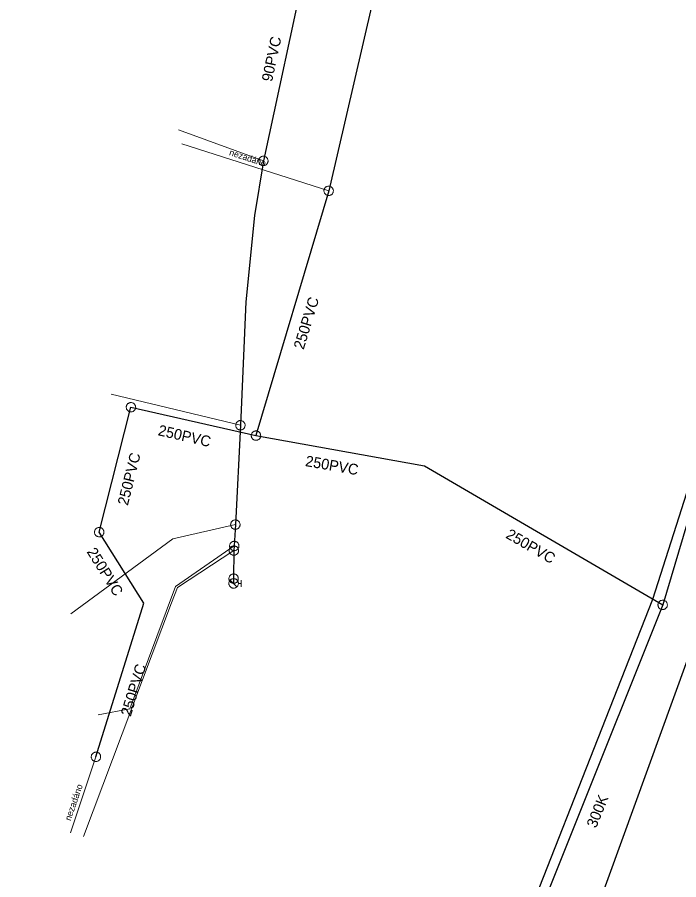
# Model space of a CAD drawing. Extents: x -741806 to -738704, y -1059275 to -1055387.
# Drawn here: x -740595 to -740533.4, y -1057880.2 to -1057799.9 of the extents above; entities that cross this region are included whole.
import ezdxf

# ---------------------------------------------------------------- set-up
doc = ezdxf.new("R2010")
doc.units = 0
doc.header["$LTSCALE"] = 0.4
for name, color, linetype, lineweight in [('2', 7, 'Continuous', 25), ('21', 7, 'Continuous', 13), ('3', 7, 'Continuous', 13), ('50', 7, 'Continuous', 13), ('51', 7, 'Continuous', 13), ('52', 7, 'Continuous', 25), ('56', 7, 'Continuous', 13)]:
    doc.layers.add(name, color=color, linetype=linetype, lineweight=lineweight)
for name, color, linetype in [('5', 7, 'Continuous'), ('53', 7, 'Continuous'), ('55', 7, 'Continuous')]:
    doc.layers.add(name, color=color, linetype=linetype)

msp = doc.modelspace()

# ---------------------------------------------------------------- linework, layer by layer
at = {"layer": '2'}
for p, q in [((-740566.01, -1057816.08), (-740572.78, -1057838.879)), ((-740584.42, -1057836.24), (-740572.78, -1057838.879)), ((-740529.84, -1057837.59), (-740534.91, -1057854.649)), ((-740572.78, -1057838.879), (-740557.1, -1057841.679)), ((-740557.1, -1057841.679), (-740534.91, -1057854.649)), ((-740587.68, -1057868.8), (-740583.21, -1057854.49))]:
    msp.add_line(p, q, dxfattribs=at)
for points in [[(-740609.006, -1057979.487), (-740608.671, -1057978.605), (-740585.671, -1057978.608), (-740567.046, -1057933.639), (-740552.184, -1057895.72), (-740535.835, -1057854.115), (-740530.462, -1057837.318), (-740525.059, -1057820.845), (-740524.232, -1057813.604), (-740512.355, -1057767.872), (-740507.212, -1057752.35), (-740500.784, -1057723.652), (-740491.688, -1057677.854), (-740489.039, -1057665.21)], [(-740555.449, -1057770.34), (-740559.17, -1057786.49), (-740559.609, -1057788.399), (-740566.01, -1057816.08)], [(-740583.21, -1057854.49), (-740587.379, -1057847.87), (-740584.42, -1057836.24)], [(-740534.91, -1057854.649), (-740551.41, -1057895.909), (-740566.21, -1057933.99)]]:
    msp.add_lwpolyline(points, dxfattribs=at)
at = {"layer": '21'}
for p, q in [((-740572.09, -1057813.29), (-740580, -1057810.399)), ((-740574.23, -1057837.919), (-740586.26, -1057835.02))]:
    msp.add_line(p, q, dxfattribs=at)
for points in [[(-740574.699, -1057847.169), (-740580.53, -1057848.49), (-740590.02, -1057855.48)], [(-740574.84, -1057849.59), (-740580.1, -1057853.02), (-740580.66, -1057854.47), (-740588.829, -1057876.21)], [(-740574.8, -1057849.159), (-740580.28, -1057852.919), (-740584.539, -1057864.33), (-740587.46, -1057864.899)]]:
    msp.add_lwpolyline(points, dxfattribs=at)
at = {"layer": '3'}
for points in [[(-740566.109, -1057816.506), (-740566.064, -1057816.513), (-740566.019, -1057816.517), (-740565.972, -1057816.515), (-740565.928, -1057816.509), (-740565.883, -1057816.498), (-740565.839, -1057816.482), (-740565.799, -1057816.462), (-740565.759, -1057816.438), (-740565.724, -1057816.409), (-740565.691, -1057816.378), (-740565.661, -1057816.343), (-740565.635, -1057816.305), (-740565.614, -1057816.264), (-740565.597, -1057816.222), (-740565.584, -1057816.178), (-740565.576, -1057816.133), (-740565.573, -1057816.087), (-740565.574, -1057816.042), (-740565.581, -1057815.996), (-740565.592, -1057815.951), (-740565.608, -1057815.909), (-740565.628, -1057815.868), (-740565.652, -1057815.829), (-740565.68, -1057815.792), (-740565.712, -1057815.759), (-740565.748, -1057815.731), (-740565.785, -1057815.704), (-740565.826, -1057815.683), (-740565.868, -1057815.666), (-740565.913, -1057815.653), (-740565.957, -1057815.645), (-740566.002, -1057815.642), (-740566.049, -1057815.643), (-740566.095, -1057815.65), (-740566.138, -1057815.661), (-740566.182, -1057815.676), (-740566.222, -1057815.697), (-740566.262, -1057815.721), (-740566.297, -1057815.749), (-740566.33, -1057815.781), (-740566.36, -1057815.816), (-740566.386, -1057815.854), (-740566.407, -1057815.894), (-740566.424, -1057815.936), (-740566.437, -1057815.981), (-740566.445, -1057816.026), (-740566.448, -1057816.071), (-740566.447, -1057816.117), (-740566.44, -1057816.163), (-740566.429, -1057816.207), (-740566.413, -1057816.25), (-740566.394, -1057816.291), (-740566.369, -1057816.33), (-740566.341, -1057816.366), (-740566.309, -1057816.399), (-740566.274, -1057816.429), (-740566.236, -1057816.454), (-740566.195, -1057816.476), (-740566.153, -1057816.493), (-740566.11, -1057816.506)], [(-740584.311, -1057835.815), (-740584.355, -1057835.807), (-740584.401, -1057835.803), (-740584.447, -1057835.803), (-740584.492, -1057835.808), (-740584.537, -1057835.819), (-740584.581, -1057835.833), (-740584.622, -1057835.853), (-740584.662, -1057835.876), (-740584.698, -1057835.903), (-740584.731, -1057835.934), (-740584.762, -1057835.969), (-740584.789, -1057836.006), (-740584.81, -1057836.046), (-740584.829, -1057836.088), (-740584.843, -1057836.132), (-740584.852, -1057836.177), (-740584.855, -1057836.222), (-740584.855, -1057836.268), (-740584.85, -1057836.314), (-740584.839, -1057836.359), (-740584.824, -1057836.402), (-740584.806, -1057836.442), (-740584.782, -1057836.483), (-740584.755, -1057836.519), (-740584.724, -1057836.553), (-740584.689, -1057836.583), (-740584.652, -1057836.609), (-740584.612, -1057836.632), (-740584.57, -1057836.65), (-740584.526, -1057836.663), (-740584.482, -1057836.673), (-740584.436, -1057836.677), (-740584.39, -1057836.676), (-740584.344, -1057836.67), (-740584.3, -1057836.661), (-740584.256, -1057836.646), (-740584.215, -1057836.627), (-740584.175, -1057836.603), (-740584.139, -1057836.576), (-740584.106, -1057836.545), (-740584.075, -1057836.511), (-740584.048, -1057836.473), (-740584.026, -1057836.434), (-740584.008, -1057836.392), (-740583.995, -1057836.348), (-740583.985, -1057836.303), (-740583.981, -1057836.257), (-740583.982, -1057836.212), (-740583.987, -1057836.166), (-740583.998, -1057836.121), (-740584.013, -1057836.078), (-740584.031, -1057836.036), (-740584.055, -1057835.997), (-740584.082, -1057835.96), (-740584.113, -1057835.926), (-740584.148, -1057835.896), (-740584.185, -1057835.87), (-740584.225, -1057835.847), (-740584.267, -1057835.829), (-740584.31, -1057835.815)], [(-740572.352, -1057838.976), (-740572.345, -1057838.931), (-740572.342, -1057838.886), (-740572.344, -1057838.839), (-740572.35, -1057838.795), (-740572.362, -1057838.75), (-740572.378, -1057838.707), (-740572.398, -1057838.666), (-740572.422, -1057838.627), (-740572.451, -1057838.592), (-740572.482, -1057838.559), (-740572.518, -1057838.529), (-740572.556, -1057838.503), (-740572.596, -1057838.483), (-740572.639, -1057838.465), (-740572.683, -1057838.453), (-740572.728, -1057838.445), (-740572.774, -1057838.442), (-740572.819, -1057838.443), (-740572.865, -1057838.45), (-740572.91, -1057838.462), (-740572.952, -1057838.478), (-740572.992, -1057838.497), (-740573.032, -1057838.522), (-740573.068, -1057838.55), (-740573.101, -1057838.583), (-740573.13, -1057838.618), (-740573.155, -1057838.655), (-740573.177, -1057838.697), (-740573.194, -1057838.739), (-740573.206, -1057838.783), (-740573.214, -1057838.828), (-740573.217, -1057838.873), (-740573.215, -1057838.92), (-740573.208, -1057838.965), (-740573.198, -1057839.009), (-740573.182, -1057839.052), (-740573.161, -1057839.093), (-740573.136, -1057839.132), (-740573.109, -1057839.167), (-740573.077, -1057839.2), (-740573.042, -1057839.23), (-740573.004, -1057839.256), (-740572.963, -1057839.277), (-740572.921, -1057839.294), (-740572.876, -1057839.306), (-740572.831, -1057839.314), (-740572.786, -1057839.317), (-740572.74, -1057839.316), (-740572.694, -1057839.308), (-740572.65, -1057839.297), (-740572.607, -1057839.281), (-740572.566, -1057839.262), (-740572.527, -1057839.237), (-740572.491, -1057839.209), (-740572.458, -1057839.176), (-740572.429, -1057839.141), (-740572.404, -1057839.104), (-740572.382, -1057839.062), (-740572.366, -1057839.02), (-740572.353, -1057838.977)], [(-740587.612, -1057847.499), (-740587.648, -1057847.525), (-740587.682, -1057847.555), (-740587.714, -1057847.589), (-740587.741, -1057847.625), (-740587.765, -1057847.665), (-740587.784, -1057847.707), (-740587.798, -1057847.75), (-740587.809, -1057847.795), (-740587.814, -1057847.84), (-740587.815, -1057847.885), (-740587.811, -1057847.931), (-740587.802, -1057847.977), (-740587.788, -1057848.02), (-740587.771, -1057848.062), (-740587.748, -1057848.102), (-740587.722, -1057848.14), (-740587.691, -1057848.174), (-740587.658, -1057848.205), (-740587.621, -1057848.233), (-740587.581, -1057848.256), (-740587.54, -1057848.275), (-740587.497, -1057848.29), (-740587.452, -1057848.3), (-740587.407, -1057848.306), (-740587.361, -1057848.306), (-740587.315, -1057848.301), (-740587.271, -1057848.293), (-740587.226, -1057848.279), (-740587.184, -1057848.261), (-740587.144, -1057848.238), (-740587.107, -1057848.213), (-740587.073, -1057848.183), (-740587.041, -1057848.149), (-740587.014, -1057848.111), (-740586.991, -1057848.073), (-740586.971, -1057848.031), (-740586.957, -1057847.988), (-740586.947, -1057847.943), (-740586.942, -1057847.898), (-740586.941, -1057847.853), (-740586.945, -1057847.807), (-740586.953, -1057847.761), (-740586.967, -1057847.718), (-740586.985, -1057847.676), (-740587.007, -1057847.636), (-740587.034, -1057847.598), (-740587.064, -1057847.564), (-740587.097, -1057847.533), (-740587.134, -1057847.505), (-740587.174, -1057847.482), (-740587.216, -1057847.463), (-740587.258, -1057847.448), (-740587.303, -1057847.438), (-740587.348, -1057847.432), (-740587.395, -1057847.432), (-740587.441, -1057847.436), (-740587.485, -1057847.445), (-740587.529, -1057847.459), (-740587.571, -1057847.477), (-740587.611, -1057847.498)], [(-740535.035, -1057855.068), (-740534.991, -1057855.078), (-740534.946, -1057855.084), (-740534.899, -1057855.086), (-740534.854, -1057855.082), (-740534.809, -1057855.074), (-740534.764, -1057855.061), (-740534.723, -1057855.043), (-740534.682, -1057855.022), (-740534.645, -1057854.995), (-740534.61, -1057854.966), (-740534.578, -1057854.933), (-740534.55, -1057854.896), (-740534.527, -1057854.857), (-740534.506, -1057854.816), (-740534.491, -1057854.773), (-740534.48, -1057854.728), (-740534.475, -1057854.683), (-740534.473, -1057854.637), (-740534.477, -1057854.591), (-740534.485, -1057854.546), (-740534.498, -1057854.503), (-740534.515, -1057854.461), (-740534.537, -1057854.42), (-740534.563, -1057854.382), (-740534.593, -1057854.347), (-740534.627, -1057854.316), (-740534.662, -1057854.288), (-740534.702, -1057854.264), (-740534.743, -1057854.244), (-740534.786, -1057854.229), (-740534.83, -1057854.218), (-740534.875, -1057854.212), (-740534.922, -1057854.211), (-740534.968, -1057854.215), (-740535.012, -1057854.223), (-740535.056, -1057854.236), (-740535.098, -1057854.253), (-740535.139, -1057854.276), (-740535.176, -1057854.301), (-740535.211, -1057854.33), (-740535.243, -1057854.364), (-740535.271, -1057854.4), (-740535.295, -1057854.439), (-740535.315, -1057854.48), (-740535.33, -1057854.524), (-740535.341, -1057854.568), (-740535.347, -1057854.613), (-740535.348, -1057854.659), (-740535.344, -1057854.705), (-740535.336, -1057854.75), (-740535.323, -1057854.794), (-740535.306, -1057854.836), (-740535.283, -1057854.876), (-740535.258, -1057854.914), (-740535.228, -1057854.949), (-740535.195, -1057854.981), (-740535.159, -1057855.008), (-740535.119, -1057855.033), (-740535.078, -1057855.052), (-740535.036, -1057855.068)], [(-740587.548, -1057868.382), (-740587.592, -1057868.371), (-740587.637, -1057868.364), (-740587.684, -1057868.362), (-740587.729, -1057868.365), (-740587.774, -1057868.373), (-740587.819, -1057868.385), (-740587.861, -1057868.402), (-740587.902, -1057868.423), (-740587.939, -1057868.449), (-740587.975, -1057868.478), (-740588.007, -1057868.511), (-740588.036, -1057868.547), (-740588.059, -1057868.585), (-740588.081, -1057868.626), (-740588.096, -1057868.669), (-740588.108, -1057868.714), (-740588.114, -1057868.759), (-740588.116, -1057868.804), (-740588.113, -1057868.851), (-740588.105, -1057868.896), (-740588.093, -1057868.94), (-740588.076, -1057868.981), (-740588.055, -1057869.023), (-740588.03, -1057869.061), (-740588, -1057869.096), (-740587.967, -1057869.128), (-740587.932, -1057869.156), (-740587.893, -1057869.181), (-740587.852, -1057869.201), (-740587.808, -1057869.217), (-740587.765, -1057869.229), (-740587.72, -1057869.235), (-740587.673, -1057869.237), (-740587.627, -1057869.234), (-740587.583, -1057869.227), (-740587.538, -1057869.214), (-740587.496, -1057869.197), (-740587.455, -1057869.176), (-740587.418, -1057869.151), (-740587.383, -1057869.122), (-740587.35, -1057869.089), (-740587.321, -1057869.053), (-740587.297, -1057869.014), (-740587.277, -1057868.974), (-740587.261, -1057868.93), (-740587.249, -1057868.886), (-740587.242, -1057868.841), (-740587.241, -1057868.795), (-740587.244, -1057868.749), (-740587.252, -1057868.704), (-740587.264, -1057868.66), (-740587.28, -1057868.617), (-740587.302, -1057868.577), (-740587.327, -1057868.539), (-740587.357, -1057868.503), (-740587.39, -1057868.471), (-740587.425, -1057868.443), (-740587.465, -1057868.418), (-740587.505, -1057868.398), (-740587.547, -1057868.382)]]:
    msp.add_lwpolyline(points, dxfattribs=at)
at = {"layer": '50'}
for p, q in [((-740574.863, -1057852.648), (-740575.18, -1057852.331)), ((-740574.863, -1057852.648), (-740574.551, -1057852.964)), ((-740574.416, -1057852.648), (-740574.165, -1057852.648)), ((-740574.165, -1057852.34), (-740574.165, -1057852.648)), ((-740574.165, -1057852.955), (-740574.165, -1057852.648))]:
    msp.add_line(p, q, dxfattribs=at)
msp.add_lwpolyline([(-740574.867, -1057853.092), (-740574.818, -1057853.09), (-740574.772, -1057853.085), (-740574.726, -1057853.072), (-740574.683, -1057853.055), (-740574.643, -1057853.036), (-740574.602, -1057853.009), (-740574.567, -1057852.98), (-740574.532, -1057852.947), (-740574.502, -1057852.912), (-740574.478, -1057852.872), (-740574.456, -1057852.831), (-740574.437, -1057852.788), (-740574.427, -1057852.742), (-740574.419, -1057852.696), (-740574.416, -1057852.65), (-740574.419, -1057852.604), (-740574.424, -1057852.559), (-740574.437, -1057852.513), (-740574.454, -1057852.469), (-740574.475, -1057852.426), (-740574.5, -1057852.388), (-740574.529, -1057852.351), (-740574.562, -1057852.318), (-740574.597, -1057852.289), (-740574.637, -1057852.262), (-740574.678, -1057852.24), (-740574.721, -1057852.224), (-740574.767, -1057852.21), (-740574.813, -1057852.205), (-740574.859, -1057852.198), (-740574.907, -1057852.201), (-740574.953, -1057852.209), (-740574.996, -1057852.22), (-740575.042, -1057852.236), (-740575.083, -1057852.258), (-740575.123, -1057852.282), (-740575.158, -1057852.312), (-740575.193, -1057852.344), (-740575.223, -1057852.382), (-740575.247, -1057852.42), (-740575.269, -1057852.463), (-740575.285, -1057852.506), (-740575.299, -1057852.549), (-740575.307, -1057852.598), (-740575.31, -1057852.644), (-740575.307, -1057852.69), (-740575.299, -1057852.736), (-740575.288, -1057852.782), (-740575.272, -1057852.825), (-740575.25, -1057852.868), (-740575.226, -1057852.906), (-740575.196, -1057852.944), (-740575.164, -1057852.976), (-740575.129, -1057853.006), (-740575.088, -1057853.03), (-740575.048, -1057853.054), (-740575.004, -1057853.071), (-740574.959, -1057853.081), (-740574.913, -1057853.089)], close=True, dxfattribs=at)
at = {"layer": '51'}
for points in [[(-740572.182, -1057813.717), (-740572.137, -1057813.724), (-740572.092, -1057813.727), (-740572.045, -1057813.724), (-740572.001, -1057813.718), (-740571.956, -1057813.706), (-740571.913, -1057813.689), (-740571.873, -1057813.668), (-740571.834, -1057813.644), (-740571.799, -1057813.615), (-740571.766, -1057813.583), (-740571.737, -1057813.547), (-740571.712, -1057813.509), (-740571.691, -1057813.468), (-740571.674, -1057813.426), (-740571.663, -1057813.381), (-740571.655, -1057813.336), (-740571.652, -1057813.29), (-740571.655, -1057813.245), (-740571.663, -1057813.199), (-740571.674, -1057813.155), (-740571.691, -1057813.112), (-740571.711, -1057813.071), (-740571.736, -1057813.033), (-740571.764, -1057812.997), (-740571.797, -1057812.965), (-740571.833, -1057812.935), (-740571.871, -1057812.911), (-740571.912, -1057812.89), (-740571.955, -1057812.874), (-740571.999, -1057812.861), (-740572.044, -1057812.854), (-740572.089, -1057812.852), (-740572.136, -1057812.854), (-740572.18, -1057812.861), (-740572.225, -1057812.873), (-740572.268, -1057812.889), (-740572.308, -1057812.91), (-740572.347, -1057812.935), (-740572.382, -1057812.964), (-740572.415, -1057812.996), (-740572.444, -1057813.031), (-740572.469, -1057813.07), (-740572.489, -1057813.111), (-740572.507, -1057813.153), (-740572.518, -1057813.197), (-740572.526, -1057813.243), (-740572.528, -1057813.289), (-740572.526, -1057813.334), (-740572.518, -1057813.38), (-740572.507, -1057813.424), (-740572.49, -1057813.466), (-740572.47, -1057813.507), (-740572.445, -1057813.546), (-740572.417, -1057813.581), (-740572.384, -1057813.614), (-740572.348, -1057813.643), (-740572.31, -1057813.668), (-740572.269, -1057813.689), (-740572.226, -1057813.705), (-740572.183, -1057813.716)], [(-740574.654, -1057837.816), (-740574.663, -1057837.86), (-740574.667, -1057837.905), (-740574.665, -1057837.952), (-740574.66, -1057837.996), (-740574.649, -1057838.041), (-740574.634, -1057838.085), (-740574.614, -1057838.126), (-740574.59, -1057838.165), (-740574.562, -1057838.201), (-740574.531, -1057838.234), (-740574.496, -1057838.264), (-740574.458, -1057838.291), (-740574.418, -1057838.313), (-740574.376, -1057838.33), (-740574.332, -1057838.343), (-740574.287, -1057838.352), (-740574.241, -1057838.355), (-740574.196, -1057838.354), (-740574.15, -1057838.348), (-740574.105, -1057838.337), (-740574.062, -1057838.321), (-740574.021, -1057838.303), (-740573.982, -1057838.278), (-740573.945, -1057838.251), (-740573.912, -1057838.219), (-740573.882, -1057838.184), (-740573.857, -1057838.147), (-740573.834, -1057838.106), (-740573.817, -1057838.064), (-740573.803, -1057838.02), (-740573.796, -1057837.975), (-740573.792, -1057837.93), (-740573.793, -1057837.883), (-740573.799, -1057837.839), (-740573.81, -1057837.794), (-740573.825, -1057837.75), (-740573.845, -1057837.709), (-740573.868, -1057837.67), (-740573.897, -1057837.634), (-740573.928, -1057837.601), (-740573.963, -1057837.571), (-740574, -1057837.544), (-740574.041, -1057837.523), (-740574.082, -1057837.505), (-740574.127, -1057837.492), (-740574.172, -1057837.483), (-740574.218, -1057837.481), (-740574.263, -1057837.481), (-740574.309, -1057837.487), (-740574.353, -1057837.498), (-740574.396, -1057837.514), (-740574.438, -1057837.532), (-740574.477, -1057837.557), (-740574.513, -1057837.584), (-740574.547, -1057837.616), (-740574.577, -1057837.651), (-740574.602, -1057837.688), (-740574.624, -1057837.729), (-740574.641, -1057837.771), (-740574.654, -1057837.815)], [(-740575.125, -1057847.265), (-740575.113, -1057847.308), (-740575.096, -1057847.35), (-740575.075, -1057847.392), (-740575.05, -1057847.429), (-740575.02, -1057847.464), (-740574.987, -1057847.497), (-740574.951, -1057847.525), (-740574.913, -1057847.55), (-740574.871, -1057847.569), (-740574.829, -1057847.585), (-740574.784, -1057847.596), (-740574.738, -1057847.604), (-740574.693, -1057847.606), (-740574.647, -1057847.602), (-740574.602, -1057847.594), (-740574.558, -1057847.582), (-740574.515, -1057847.565), (-740574.475, -1057847.544), (-740574.437, -1057847.518), (-740574.402, -1057847.488), (-740574.37, -1057847.456), (-740574.341, -1057847.42), (-740574.317, -1057847.381), (-740574.297, -1057847.34), (-740574.281, -1057847.297), (-740574.269, -1057847.252), (-740574.263, -1057847.208), (-740574.261, -1057847.161), (-740574.264, -1057847.116), (-740574.272, -1057847.07), (-740574.285, -1057847.027), (-740574.301, -1057846.985), (-740574.323, -1057846.944), (-740574.348, -1057846.906), (-740574.377, -1057846.871), (-740574.41, -1057846.838), (-740574.446, -1057846.81), (-740574.485, -1057846.785), (-740574.526, -1057846.766), (-740574.569, -1057846.75), (-740574.613, -1057846.739), (-740574.659, -1057846.731), (-740574.704, -1057846.73), (-740574.75, -1057846.733), (-740574.795, -1057846.741), (-740574.84, -1057846.753), (-740574.882, -1057846.771), (-740574.922, -1057846.791), (-740574.961, -1057846.817), (-740574.996, -1057846.847), (-740575.027, -1057846.88), (-740575.056, -1057846.915), (-740575.08, -1057846.954), (-740575.101, -1057846.995), (-740575.117, -1057847.038), (-740575.128, -1057847.083), (-740575.134, -1057847.127), (-740575.136, -1057847.174), (-740575.133, -1057847.219), (-740575.125, -1057847.264)], [(-740575.16, -1057849.405), (-740575.133, -1057849.441), (-740575.102, -1057849.474), (-740575.066, -1057849.505), (-740575.029, -1057849.53), (-740574.989, -1057849.552), (-740574.946, -1057849.57), (-740574.903, -1057849.583), (-740574.858, -1057849.592), (-740574.812, -1057849.595), (-740574.767, -1057849.594), (-740574.721, -1057849.588), (-740574.676, -1057849.577), (-740574.633, -1057849.562), (-740574.592, -1057849.543), (-740574.553, -1057849.518), (-740574.516, -1057849.491), (-740574.483, -1057849.46), (-740574.453, -1057849.425), (-740574.427, -1057849.386), (-740574.405, -1057849.346), (-740574.388, -1057849.304), (-740574.374, -1057849.26), (-740574.367, -1057849.215), (-740574.362, -1057849.17), (-740574.364, -1057849.123), (-740574.37, -1057849.078), (-740574.38, -1057849.034), (-740574.396, -1057848.99), (-740574.416, -1057848.949), (-740574.439, -1057848.909), (-740574.467, -1057848.874), (-740574.498, -1057848.841), (-740574.534, -1057848.811), (-740574.571, -1057848.785), (-740574.611, -1057848.763), (-740574.654, -1057848.745), (-740574.698, -1057848.733), (-740574.743, -1057848.724), (-740574.788, -1057848.721), (-740574.834, -1057848.722), (-740574.879, -1057848.728), (-740574.924, -1057848.738), (-740574.967, -1057848.754), (-740575.009, -1057848.773), (-740575.048, -1057848.797), (-740575.084, -1057848.825), (-740575.117, -1057848.857), (-740575.147, -1057848.891), (-740575.173, -1057848.929), (-740575.195, -1057848.969), (-740575.212, -1057849.012), (-740575.226, -1057849.055), (-740575.234, -1057849.1), (-740575.238, -1057849.146), (-740575.236, -1057849.192), (-740575.23, -1057849.238), (-740575.22, -1057849.281), (-740575.204, -1057849.325), (-740575.184, -1057849.366), (-740575.161, -1057849.405)], [(-740575.206, -1057849.828), (-740575.18, -1057849.864), (-740575.149, -1057849.898), (-740575.114, -1057849.929), (-740575.078, -1057849.956), (-740575.038, -1057849.979), (-740574.996, -1057849.998), (-740574.953, -1057850.011), (-740574.908, -1057850.021), (-740574.862, -1057850.025), (-740574.817, -1057850.025), (-740574.771, -1057850.021), (-740574.726, -1057850.011), (-740574.682, -1057849.997), (-740574.641, -1057849.979), (-740574.601, -1057849.955), (-740574.564, -1057849.928), (-740574.53, -1057849.898), (-740574.499, -1057849.864), (-740574.473, -1057849.826), (-740574.45, -1057849.786), (-740574.432, -1057849.744), (-740574.417, -1057849.701), (-740574.408, -1057849.656), (-740574.403, -1057849.611), (-740574.403, -1057849.565), (-740574.408, -1057849.519), (-740574.418, -1057849.475), (-740574.432, -1057849.431), (-740574.451, -1057849.389), (-740574.473, -1057849.349), (-740574.501, -1057849.313), (-740574.531, -1057849.279), (-740574.566, -1057849.248), (-740574.602, -1057849.221), (-740574.642, -1057849.199), (-740574.684, -1057849.18), (-740574.728, -1057849.166), (-740574.772, -1057849.156), (-740574.818, -1057849.152), (-740574.863, -1057849.152), (-740574.909, -1057849.157), (-740574.954, -1057849.166), (-740574.997, -1057849.181), (-740575.039, -1057849.199), (-740575.079, -1057849.222), (-740575.116, -1057849.249), (-740575.15, -1057849.28), (-740575.181, -1057849.314), (-740575.207, -1057849.351), (-740575.23, -1057849.391), (-740575.248, -1057849.433), (-740575.263, -1057849.476), (-740575.272, -1057849.521), (-740575.277, -1057849.566), (-740575.277, -1057849.613), (-740575.272, -1057849.658), (-740575.263, -1057849.702), (-740575.248, -1057849.747), (-740575.229, -1057849.788), (-740575.206, -1057849.827)], [(-740574.862, -1057852.636), (-740574.817, -1057852.635), (-740574.772, -1057852.628), (-740574.727, -1057852.617), (-740574.685, -1057852.601), (-740574.644, -1057852.58), (-740574.605, -1057852.555), (-740574.569, -1057852.527), (-740574.536, -1057852.495), (-740574.508, -1057852.459), (-740574.483, -1057852.421), (-740574.461, -1057852.381), (-740574.444, -1057852.338), (-740574.432, -1057852.294), (-740574.424, -1057852.249), (-740574.422, -1057852.203), (-740574.424, -1057852.157), (-740574.43, -1057852.112), (-740574.442, -1057852.068), (-740574.459, -1057852.025), (-740574.479, -1057851.983), (-740574.504, -1057851.945), (-740574.532, -1057851.909), (-740574.565, -1057851.877), (-740574.599, -1057851.847), (-740574.638, -1057851.822), (-740574.679, -1057851.801), (-740574.721, -1057851.785), (-740574.766, -1057851.772), (-740574.811, -1057851.765), (-740574.857, -1057851.762), (-740574.902, -1057851.764), (-740574.947, -1057851.771), (-740574.992, -1057851.782), (-740575.034, -1057851.798), (-740575.075, -1057851.819), (-740575.114, -1057851.844), (-740575.15, -1057851.872), (-740575.183, -1057851.904), (-740575.211, -1057851.94), (-740575.236, -1057851.978), (-740575.258, -1057852.018), (-740575.275, -1057852.061), (-740575.286, -1057852.105), (-740575.295, -1057852.15), (-740575.297, -1057852.196), (-740575.295, -1057852.242), (-740575.288, -1057852.287), (-740575.277, -1057852.331), (-740575.26, -1057852.374), (-740575.24, -1057852.416), (-740575.215, -1057852.454), (-740575.187, -1057852.49), (-740575.154, -1057852.522), (-740575.12, -1057852.552), (-740575.081, -1057852.577), (-740575.04, -1057852.598), (-740574.998, -1057852.614), (-740574.953, -1057852.627), (-740574.908, -1057852.634), (-740574.863, -1057852.636)]]:
    msp.add_lwpolyline(points, dxfattribs=at)
at = {"layer": '52'}
for points in [[(-740489.868, -1057679.99), (-740497.519, -1057704.287), (-740502.89, -1057727.946), (-740504.09, -1057731.52), (-740504.16, -1057731.78), (-740504.295, -1057732.394), (-740505.458, -1057737.884), (-740512.487, -1057766.415), (-740507.033, -1057770.061), (-740517.328, -1057816.22), (-740521.664, -1057829.6), (-740544.85, -1057893.509), (-740554.399, -1057919.446), (-740570.451, -1057950.712), (-740592.697, -1058007.398), (-740600.714, -1058010.487), (-740613.05, -1058039.97), (-740626.485, -1058069.3)], [(-740568.079, -1057794.71), (-740568.149, -1057794.929), (-740572.09, -1057813.29), (-740572.92, -1057818.389), (-740573.71, -1057826.429), (-740574.23, -1057837.919), (-740574.699, -1057847.169), (-740574.8, -1057849.159), (-740574.84, -1057849.59), (-740574.859, -1057852.2), (-740574.859, -1057852.649)]]:
    msp.add_lwpolyline(points, dxfattribs=at)
at = {"layer": '56'}
for p, q in [((-740579.69, -1057811.69), (-740566.01, -1057816.08)), ((-740590.059, -1057875.889), (-740587.68, -1057868.8))]:
    msp.add_line(p, q, dxfattribs=at)

# ---------------------------------------------------------------- texts
at = {"layer": '5'}
for s, rotation, p in [('250PVC', 73, (-740568.345, -1057830.92)), ('250PVC', 347, (-740581.964, -1057838.832)), ('250PVC', 76, (-740584.715, -1057845.451)), ('250PVC', 350, (-740568.242, -1057841.706)), ('250PVC', 330, (-740549.596, -1057848.364)), ('250PVC', 302, (-740588.573, -1057849.699)), ('250PVC', 73, (-740584.444, -1057865.099)), ('300K', 68, (-740541.109, -1057875.5))]:
    msp.add_text(s, height=1, rotation=rotation, dxfattribs=at).set_placement(p)
at = {"layer": '53'}
msp.add_text('90PVC ', height=1, rotation=78, dxfattribs=at).set_placement((-740571.283, -1057805.968))
at = {"layer": '55'}
for rotation, p in [(342, (-740575.319, -1057812.744)), (71, (-740590.041, -1057874.799))]:
    msp.add_text('nezadáno  ', height=0.6, rotation=rotation, dxfattribs=at).set_placement(p)

doc.saveas('drawing.dxf')
